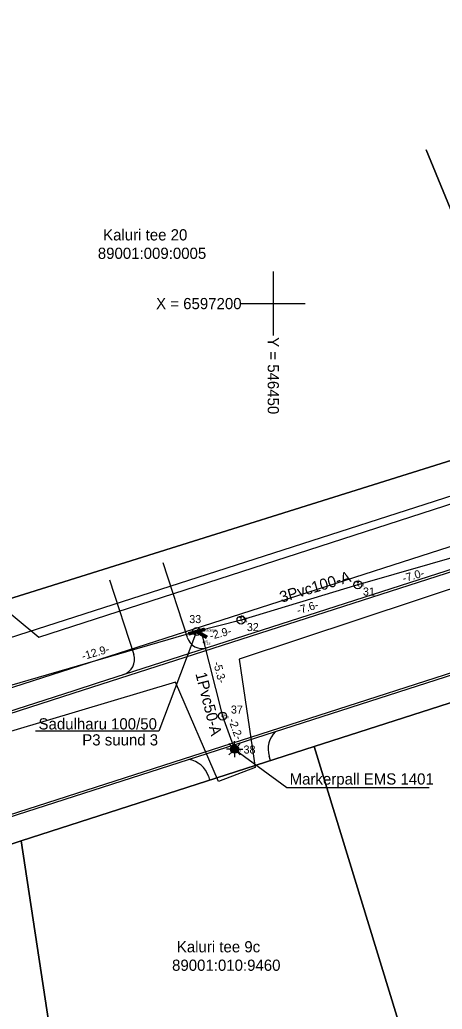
# Model space of a CAD drawing. Extents: x 546339 to 546593, y 6597108 to 6597251.
# Drawn here: x 546434.2 to 546460.5, y 6597155.9 to 6597217.7 of the extents above; entities that cross this region are included whole.
import ezdxf

# ---------------------------------------------------------------- set-up
doc = ezdxf.new("R2010")
doc.units = 0
for name, color, linetype in [('JOONSIDE', 7, 'Continuous'), ('KOORDPUNKT', 7, 'Continuous'), ('MOOTKORG-EH2000', 7, 'Continuous'), ('MOOTMPUNKT', 7, 'Continuous'), ('MOOTNR', 7, 'Continuous'), ('MOOTPIIR', 7, 'Continuous'), ('PIIR', 7, 'Continuous'), ('SIKAEV', 7, 'Continuous'), ('SITRASS', 7, 'Continuous'), ('TEE', 7, 'Continuous'), ('VORK', 7, 'Continuous')]:
    doc.layers.add(name, color=color, linetype=linetype)

msp = doc.modelspace()

# ---------------------------------------------------------------- linework, layer by layer
at = {"layer": 'KOORDPUNKT'}
for centre, radius in [((546455.281, 6597182.437), 0.25), ((546455.281, 6597182.437), 0.025), ((546455.281, 6597182.437), 0.0221), ((546455.281, 6597182.437), 0.0191), ((546455.281, 6597182.437), 0.0161), ((546455.281, 6597182.437), 0.0132), ((546455.281, 6597182.437), 0.0102), ((546455.281, 6597182.437), 0.00726), ((546455.281, 6597182.437), 0.0043), ((546447.986, 6597180.224), 0.25), ((546447.986, 6597180.224), 0.025), ((546447.986, 6597180.224), 0.0221), ((546447.986, 6597180.224), 0.0191), ((546447.986, 6597180.224), 0.0161), ((546447.986, 6597180.224), 0.0132), ((546447.986, 6597180.224), 0.0102), ((546447.986, 6597180.224), 0.00726), ((546447.986, 6597180.224), 0.0043), ((546445.217, 6597179.513), 0.25), ((546445.217, 6597179.513), 0.025), ((546445.217, 6597179.513), 0.0221), ((546445.217, 6597179.513), 0.0191), ((546445.217, 6597179.513), 0.0161), ((546445.217, 6597179.513), 0.0132), ((546445.217, 6597179.513), 0.0102), ((546445.217, 6597179.513), 0.00726), ((546445.217, 6597179.513), 0.0043), ((546446.833, 6597174.231), 0.25), ((546446.833, 6597174.231), 0.025), ((546446.833, 6597174.231), 0.0221), ((546446.833, 6597174.231), 0.0191), ((546446.833, 6597174.231), 0.0161), ((546446.833, 6597174.231), 0.0132), ((546446.833, 6597174.231), 0.0102), ((546446.833, 6597174.231), 0.00726), ((546446.833, 6597174.231), 0.0043), ((546447.589, 6597172.16), 0.25), ((546447.589, 6597172.16), 0.025), ((546447.589, 6597172.16), 0.0221), ((546447.589, 6597172.16), 0.0191), ((546447.589, 6597172.16), 0.0161), ((546447.589, 6597172.16), 0.0132), ((546447.589, 6597172.16), 0.0102), ((546447.589, 6597172.16), 0.00726), ((546447.589, 6597172.16), 0.0043)]:
    msp.add_circle(centre, radius, dxfattribs=at)
at = {"layer": 'MOOTMPUNKT'}
for centre in [(546455.259, 6597182.61), (546455.281, 6597182.437), (546447.953, 6597180.388), (546447.986, 6597180.224), (546445.217, 6597179.513), (546445.672, 6597178.84), (546446.833, 6597174.231), (546447.589, 6597172.16)]:
    msp.add_circle(centre, 0.03, dxfattribs=at)
at = {"layer": 'MOOTPIIR'}
for points in [[(546431.038, 6597182.742), (546435.363, 6597179.169), (546476.861, 6597192.584), (546477.551, 6597196.157), (546480.466, 6597197.411), (546483.506, 6597194.527), (546510.21, 6597203.146)], [(546510.398, 6597198.602), (546490.433, 6597192.051), (546491.122, 6597184.372), (546487.988, 6597183.494), (546485.449, 6597190.17), (546474.636, 6597186.911), (546476.297, 6597179.326), (546473.131, 6597178.291), (546470.279, 6597185.218), (546447.869, 6597177.79), (546448.872, 6597171.02), (546446.584, 6597170.142), (546443.888, 6597176.348), (546374.62, 6597155.63)]]:
    msp.add_lwpolyline(points, dxfattribs=at)
at = {"layer": 'PIIR'}
for points in [[(546459.55, 6597209.598), (546466.79, 6597191.98), (546491.04, 6597199.45), (546483.698, 6597217.73)], [(546424.887, 6597197.926), (546431.99, 6597181.07), (546466.79, 6597191.98), (546459.55, 6597209.598)], [(546510.07, 6597205.36), (546491.04, 6597199.45), (546466.79, 6597191.98), (546431.99, 6597181.07), (546399.93, 6597171.7), (546399.49, 6597172.55), (546362.07, 6597160.42), (546350.54, 6597167.22), (546341.457, 6597167.537)], [(546339.379, 6597150.424), (546339.82, 6597150.4), (546343.3, 6597148.09), (546350.66, 6597143.2), (546387.61, 6597151.42), (546402.5, 6597155.95), (546434.27, 6597166.43), (546452.55, 6597172.32), (546467.66, 6597177.18), (546479.16, 6597180.72), (546505.65, 6597188.82)], [(546486.042, 6597158.239), (546479.16, 6597180.72), (546467.66, 6597177.18), (546452.55, 6597172.32), (546459.381, 6597150.05)], [(546459.381, 6597150.05), (546452.55, 6597172.32), (546434.27, 6597166.43), (546437.756, 6597143.407)], [(546437.756, 6597143.407), (546434.27, 6597166.43), (546402.5, 6597155.95), (546405.647, 6597133.544)]]:
    msp.add_lwpolyline(points, dxfattribs=at)
at = {"layer": 'SITRASS'}
for p, q in [((546444.716, 6597179.446), (546445.676, 6597179.724)), ((546444.737, 6597179.374), (546445.697, 6597179.652)), ((546445.219, 6597179.592), (546445.064, 6597179.391)), ((546445.26, 6597179.604), (546445.104, 6597179.402)), ((546445.301, 6597179.615), (546445.145, 6597179.414)), ((546445.342, 6597179.627), (546445.186, 6597179.426)), ((546445.382, 6597179.639), (546445.218, 6597179.427)), ((546445.423, 6597179.651), (546445.24, 6597179.415)), ((546445.464, 6597179.662), (546445.262, 6597179.402)), ((546445.505, 6597179.674), (546445.285, 6597179.39)), ((546445.545, 6597179.686), (546445.307, 6597179.378)), ((546445.586, 6597179.698), (546445.43, 6597179.497)), ((546445.627, 6597179.71), (546445.471, 6597179.508)), ((546445.667, 6597179.721), (546445.512, 6597179.52)), ((546445.683, 6597179.701), (546445.552, 6597179.532)), ((546445.692, 6597179.671), (546445.593, 6597179.544)), ((546445.7, 6597179.641), (546445.634, 6597179.556)), ((546445.709, 6597179.612), (546445.675, 6597179.567)), ((546445.718, 6597179.58), (546445.676, 6597179.724)), ((546444.716, 6597179.446), (546444.758, 6597179.302)), ((546444.731, 6597179.45), (546444.719, 6597179.435)), ((546444.771, 6597179.462), (546444.728, 6597179.406)), ((546444.812, 6597179.474), (546444.736, 6597179.376)), ((546444.853, 6597179.486), (546444.745, 6597179.346)), ((546444.894, 6597179.497), (546444.753, 6597179.316)), ((546444.758, 6597179.302), (546445.208, 6597179.432)), ((546444.934, 6597179.509), (546444.779, 6597179.308)), ((546444.975, 6597179.521), (546444.819, 6597179.32)), ((546445.016, 6597179.533), (546444.86, 6597179.332)), ((546445.056, 6597179.545), (546444.901, 6597179.343)), ((546445.097, 6597179.556), (546444.941, 6597179.355)), ((546445.138, 6597179.568), (546444.982, 6597179.367)), ((546445.179, 6597179.58), (546445.023, 6597179.379)), ((546445.208, 6597179.432), (546445.8, 6597179.106)), ((546445.217, 6597179.513), (546445.836, 6597179.172)), ((546445.422, 6597179.486), (546445.329, 6597179.366)), ((546445.444, 6597179.474), (546445.351, 6597179.353)), ((546445.466, 6597179.461), (546445.373, 6597179.341)), ((546445.488, 6597179.449), (546445.395, 6597179.329)), ((546445.412, 6597179.491), (546445.718, 6597179.58)), ((546445.412, 6597179.491), (546445.872, 6597179.237)), ((546445.51, 6597179.437), (546445.418, 6597179.317)), ((546445.533, 6597179.425), (546445.44, 6597179.305)), ((546445.555, 6597179.412), (546445.462, 6597179.292)), ((546445.577, 6597179.4), (546445.484, 6597179.28)), ((546445.599, 6597179.388), (546445.506, 6597179.268)), ((546445.621, 6597179.376), (546445.528, 6597179.256)), ((546445.643, 6597179.364), (546445.551, 6597179.244)), ((546445.666, 6597179.351), (546445.573, 6597179.231)), ((546445.688, 6597179.339), (546445.595, 6597179.219)), ((546445.71, 6597179.327), (546445.617, 6597179.207)), ((546445.732, 6597179.315), (546445.639, 6597179.195)), ((546445.754, 6597179.303), (546445.661, 6597179.182)), ((546445.776, 6597179.29), (546445.683, 6597179.17)), ((546445.799, 6597179.278), (546445.706, 6597179.158)), ((546445.718, 6597179.582), (546445.715, 6597179.579)), ((546445.821, 6597179.266), (546445.728, 6597179.146)), ((546445.843, 6597179.254), (546445.75, 6597179.134)), ((546445.865, 6597179.241), (546445.772, 6597179.121)), ((546445.82, 6597179.143), (546445.794, 6597179.109)), ((546445.8, 6597179.106), (546445.872, 6597179.237)), ((546447.412, 6597172.337), (546447.235, 6597172.514)), ((546447.589, 6597172.41), (546447.589, 6597172.66)), ((546447.766, 6597172.337), (546447.943, 6597172.514)), ((546447.339, 6597172.16), (546447.089, 6597172.16)), ((546447.412, 6597171.983), (546447.235, 6597171.806)), ((546447.589, 6597171.91), (546447.589, 6597171.66)), ((546447.766, 6597171.983), (546447.943, 6597171.806)), ((546447.839, 6597172.16), (546448.089, 6597172.16))]:
    msp.add_line(p, q, dxfattribs=at)
for points in [[(546472.601, 6597187.97), (546470.118, 6597187.092), (546462.018, 6597184.359), (546455.281, 6597182.437), (546447.986, 6597180.224), (546445.217, 6597179.513)], [(546445.217, 6597179.513), (546432.859, 6597175.937), (546431.324, 6597175.476)], [(546445.217, 6597179.513), (546442.854, 6597173.295), (546435.16, 6597173.295)], [(546445.217, 6597179.513), (546445.545, 6597179.332), (546446.833, 6597174.231), (546447.589, 6597172.16)], [(546447.589, 6597172.16), (546450.838, 6597169.757), (546459.735, 6597169.757)]]:
    msp.add_lwpolyline(points, dxfattribs=at)
for radius in [0.25, 0.225, 0.2, 0.175, 0.15, 0.125, 0.1, 0.075, 0.05, 0.025]:
    msp.add_circle((546447.589, 6597172.16), radius, dxfattribs=at)
at = {"layer": 'TEE'}
for p, q in [((546518.272, 6597195.197), (546396.577, 6597156.011)), ((546439.027, 6597176.299), (546484.965, 6597191.091)), ((546484.87, 6597190.902), (546439.237, 6597176.208)), ((546443.112, 6597183.821), (546444.617, 6597179.149)), ((546439.781, 6597182.748), (546441.285, 6597178.076)), ((546394.646, 6597162.008), (546437.58, 6597175.833)), ((546437.484, 6597175.644), (546394.692, 6597161.865)), ((546449.834, 6597171.445), (546449.745, 6597171.734)), ((546444.724, 6597171.514), (546444.724, 6597171.514)), ((546446.026, 6597170.218), (546449.834, 6597171.445))]:
    msp.add_line(p, q, dxfattribs=at)
for points in [[(546514.456, 6597205.157), (546396.804, 6597167.285), (546396.804, 6597167.285)], [(546515.375, 6597202.301), (546397.724, 6597164.429), (546397.724, 6597164.429)], [(546396.531, 6597156.154), (546518.226, 6597195.34), (546518.226, 6597195.34)], [(546439.237, 6597176.208), (546437.484, 6597175.644), (546437.484, 6597175.644), (546437.484, 6597175.644)], [(546437.58, 6597175.833), (546437.58, 6597175.833), (546439.027, 6597176.299), (546439.027, 6597176.299)], [(546445.949, 6597170.47), (546445.949, 6597170.47), (546446.026, 6597170.218)]]:
    msp.add_lwpolyline(points, dxfattribs=at)
for centre, radius, start, end in [((546445.569, 6597179.455), 1, 197.8487, 287.84704), ((546440.333, 6597177.77), 1, 287.8487, 17.8487), ((546451.179, 6597172.175), 1.5, 133.69063, 197.08924), ((546444.515, 6597170.029), 1.5, 17.08924, 82.00676)]:
    msp.add_arc(centre, radius, start, end, dxfattribs=at)
at = {"layer": 'VORK'}
for p, q in [((546450, 6597202), (546450, 6597198)), ((546448, 6597200), (546452, 6597200))]:
    msp.add_line(p, q, dxfattribs=at)

# ---------------------------------------------------------------- texts
at = {"layer": 'JOONSIDE'}
for s, rotation, p in [('-7.0-', 15.92211, (546458.142, 6597182.581)), ('-7.6-', 16.87562, (546451.551, 6597180.58)), ('-2.9-', 14.40081, (546446.091, 6597178.993)), ('-12.9-', 16.13733, (546438.128, 6597177.722)), ('-5.3-', 284.17141, (546446.248, 6597177.57)), ('-2.2-', 290.05416, (546447.189, 6597173.986))]:
    msp.add_text(s, height=0.5, rotation=rotation, dxfattribs=at).set_placement(p)
at = {"layer": 'KOORDPUNKT'}
for s, p in [('31', (546455.599, 6597181.761)), ('33', (546444.756, 6597180.038)), ('32', (546448.352, 6597179.54)), ('37', (546447.356, 6597174.387)), ('38', (546448.146, 6597171.889))]:
    msp.add_text(s, height=0.5, dxfattribs=at).set_placement(p)
at = {"layer": 'MOOTKORG-EH2000'}
for s, p in [('6.16', (546455.259, 6597182.46)), ('6.16', (546455.281, 6597182.287)), ('6.21', (546447.953, 6597180.238)), ('6.24', (546447.986, 6597180.074)), ('6.25', (546445.217, 6597179.363)), ('6.18', (546445.672, 6597178.69)), ('6.66', (546446.833, 6597174.081)), ('6.73', (546447.589, 6597172.01))]:
    msp.add_text(s, height=0.15, dxfattribs=at).set_placement(p)
at = {"layer": 'MOOTNR'}
for s, p in [('1', (546455.259, 6597182.61)), ('1', (546455.281, 6597182.437)), ('75', (546447.953, 6597180.388)), ('100', (546447.986, 6597180.224)), ('50-100kolmik', (546445.217, 6597179.513)), ('50', (546445.672, 6597178.84)), ('50', (546446.833, 6597174.231)), ('50', (546447.589, 6597172.16))]:
    msp.add_text(s, height=0.15, dxfattribs=at).set_placement(p)
at = {"layer": 'PIIR'}
for s, p in [('Kaluri tee 20', (546439.379, 6597203.945)), ('89001:009:0005', (546439.047, 6597202.792)), ('Kaluri tee 9c', (546443.979, 6597159.467)), ('89001:010:9460', (546443.682, 6597158.314))]:
    msp.add_text(s, height=0.7, dxfattribs=at).set_placement(p)
at = {"layer": 'SIKAEV'}
msp.add_text('1Pvc50-A', height=0.7, rotation=284.17141, dxfattribs=at).set_placement((546445.135, 6597176.875))
at = {"layer": 'SITRASS'}
msp.add_text('3Pvc100-A', height=0.7, rotation=16.87562, dxfattribs=at).set_placement((546450.518, 6597181.306))
for s, p in [('Sadulharu 100/50', (546435.345, 6597173.393)), ('P3 suund 3', (546438.074, 6597172.393)), ('Markerpall EMS 1401', (546451.019, 6597169.95))]:
    msp.add_text(s, height=0.7, dxfattribs=at).set_placement(p)
at = {"layer": 'VORK'}
msp.add_text('X = 6597200', height=0.7, dxfattribs=at).set_placement((546442.685, 6597199.65))
msp.add_text('Y = 546450 ', height=0.7, rotation=270, dxfattribs=at).set_placement((546449.65, 6597197.9))

doc.saveas('drawing.dxf')
